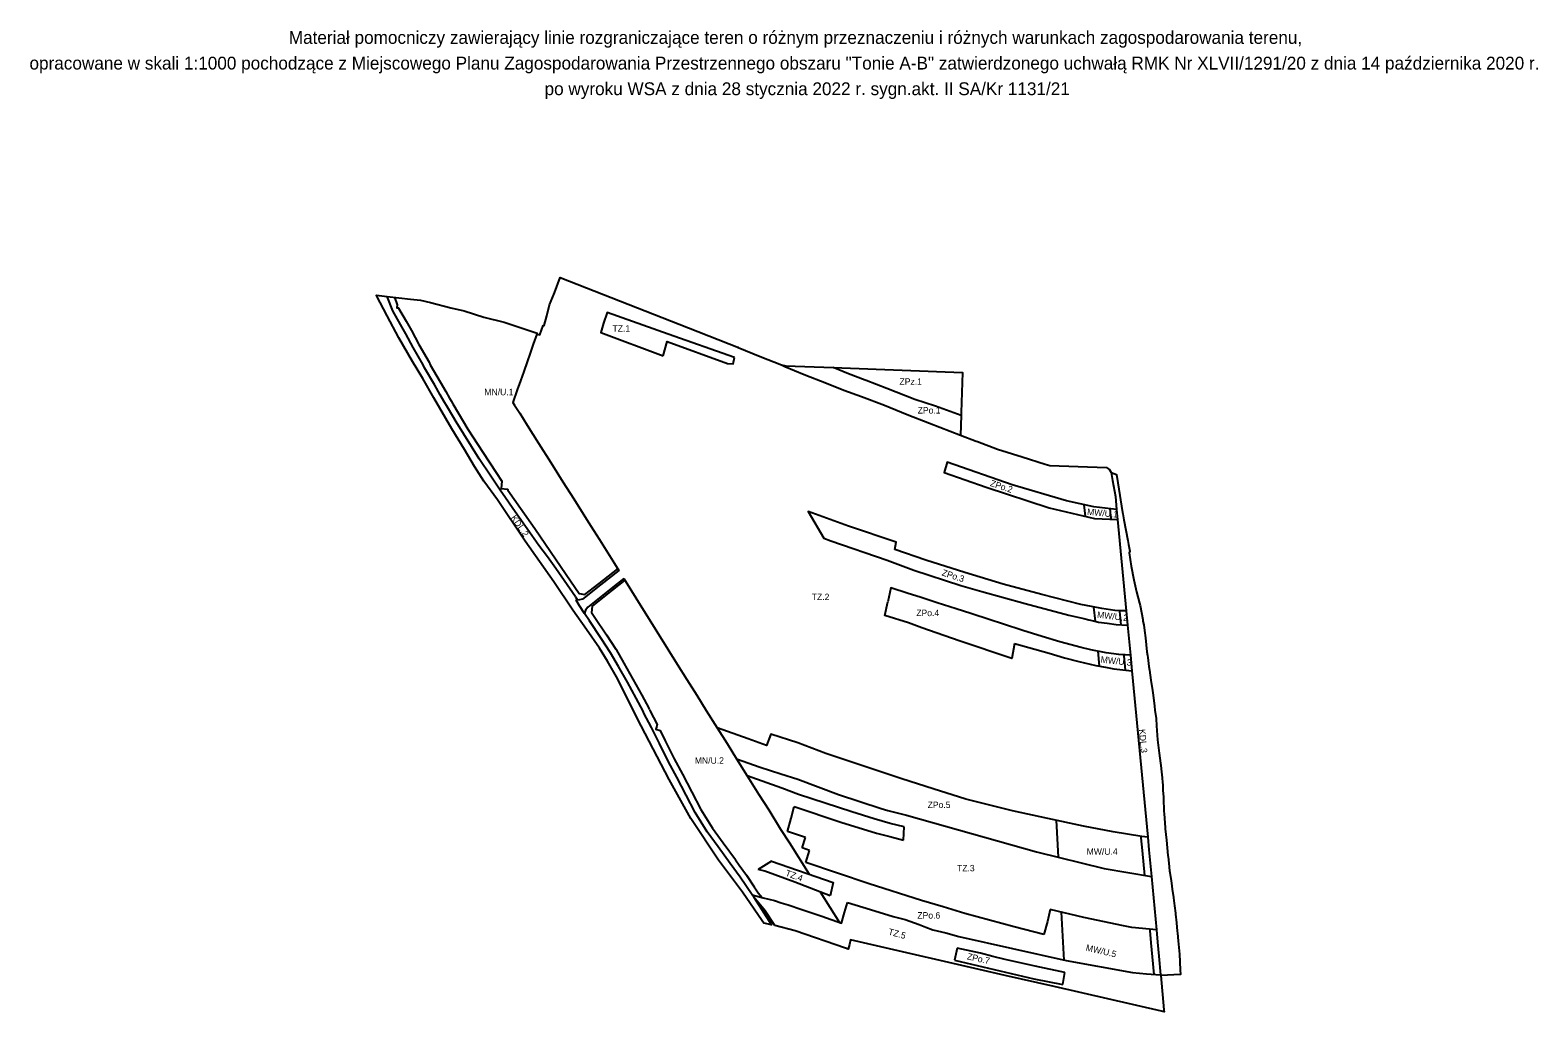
# Model space of a CAD drawing. Extents: x 7421311 to 7422722, y 5551458 to 5553094.
# Drawn here: x 7421311 to 7422722, y 5552175 to 5553094 of the extents above; entities that cross this region are included whole.
import ezdxf

# ---------------------------------------------------------------- set-up
doc = ezdxf.new("R2010")
doc.units = 0
for name, color, linetype in [('info', 7, 'Continuous'), ('linie rozgraniczające', 7, 'Continuous'), ('nieprzekraczalne linie zabudowy', 7, 'Continuous'), ('przeznaczenia terenów', 7, 'Continuous')]:
    doc.layers.add(name, color=color, linetype=linetype)

msp = doc.modelspace()

# ---------------------------------------------------------------- linework, layer by layer
at = {"layer": 'linie rozgraniczające'}
for p, q in [((7421645.3, 5552844.5), (7421645.2, 5552844.5)), ((7421650.5, 5552831), (7421645.3, 5552844.5)), ((7421657.8, 5552818.4), (7421650.5, 5552831)), ((7421662.7, 5552809.7), (7421657.8, 5552818.4)), ((7421669.7, 5552796.7), (7421662.7, 5552809.7)), ((7421679, 5552780.5), (7421669.7, 5552796.7)), ((7421694.9, 5552752.5), (7421689.7, 5552761.5)), ((7421706.6, 5552732.4), (7421701.6, 5552740.9)), ((7421709.7, 5552727.2), (7421706.6, 5552732.4)), ((7421731.4, 5552692.7), (7421709.7, 5552727.2)), ((7421709.7, 5552727.2), (7421709.7, 5552727.2)), ((7421742.2, 5552676.4), (7421731.4, 5552692.7)), ((7421731.4, 5552692.7), (7421731.4, 5552692.7)), ((7422297.1, 5552649.6), (7422298.2, 5552639)), ((7421778.4, 5552624), (7421765, 5552642.9)), ((7422149.2, 5552597.7), (7422120.1, 5552607.9)), ((7422138.1, 5552588.5), (7422182, 5552574)), ((7422185.8, 5552586.3), (7422149.2, 5552597.7)), ((7422182, 5552574), (7422182, 5552574)), ((7422221.5, 5552575.3), (7422185.8, 5552586.3)), ((7422257.9, 5552565.7), (7422221.5, 5552575.3)), ((7421821.4, 5552563.4), (7421823.2, 5552560.3)), ((7421823.2, 5552560.3), (7421823.2, 5552560.3)), ((7422294.3, 5552556.2), (7422257.9, 5552565.7)), ((7422242.3, 5552557.3), (7422283, 5552546.3)), ((7422283, 5552546.3), (7422296.9, 5552543.1)), ((7422304.1, 5552554.3), (7422294.3, 5552556.2)), ((7422326, 5552550.7), (7422313.8, 5552552.4)), ((7422331.4, 5552550.5), (7422326, 5552550.7)), ((7422326, 5552550.7), (7422326, 5552550.7)), ((7422336.7, 5552550.4), (7422331.4, 5552550.5)), ((7421845.4, 5552524.6), (7421834.5, 5552540.9)), ((7422306.2, 5552540.9), (7422310.7, 5552539.9)), ((7422319, 5552538.7), (7422327.2, 5552537.5)), ((7422310.1, 5552512.7), (7422311.5, 5552498.6)), ((7421870, 5552483.5), (7421861.6, 5552498.4)), ((7421878.2, 5552468.6), (7421870, 5552483.5)), ((7421884.9, 5552456.5), (7421878.2, 5552468.6)), ((7422014.5, 5552384.5), (7421982.2, 5552396)), ((7422030, 5552378.5), (7422014.5, 5552384.5)), ((7422080, 5552362.2), (7422030, 5552378.5)), ((7422023.2, 5552356.3), (7422026.1, 5552367.2)), ((7422026.1, 5552367.2), (7422069.8, 5552352.5)), ((7422100.9, 5552355.8), (7422080, 5552362.2)), ((7422019.7, 5552343.9), (7422023.2, 5552356.3)), ((7422069.8, 5552352.5), (7422103, 5552342.4)), ((7422128.2, 5552335.8), (7422128.8, 5552348.1)), ((7422273.4, 5552319.7), (7422271.6, 5552354.4)), ((7422036.6, 5552338.4), (7422019.7, 5552343.9)), ((7422033.6, 5552328.6), (7422036.6, 5552338.4)), ((7422040.3, 5552326.1), (7422033.6, 5552328.6)), ((7422036.8, 5552315), (7422040.3, 5552326.1)), ((7421998.5, 5552306.8), (7421992.2, 5552308.4)), ((7422026.6, 5552296.6), (7421998.5, 5552306.8)), ((7422096.2, 5552295), (7422036.8, 5552315)), ((7422059.8, 5552283.6), (7422026.6, 5552296.6)), ((7422145.1, 5552279.4), (7422096.2, 5552295)), ((7421986.7, 5552284.5), (7421986.7, 5552284.5)), ((7421986.7, 5552284.5), (7421997.1, 5552281.9)), ((7421997.1, 5552281.9), (7422007.6, 5552279.2)), ((7422007.6, 5552279.2), (7422014, 5552277.2)), ((7422014, 5552277.2), (7422020.5, 5552275.1)), ((7422073.1, 5552268.2), (7422075.9, 5552277.4)), ((7422075.9, 5552277.4), (7422097.3, 5552270.9)), ((7422165.5, 5552273.3), (7422145.1, 5552279.4)), ((7422020.5, 5552275.1), (7422033.3, 5552271)), ((7422033.3, 5552271), (7422051.8, 5552264.5)), ((7422097.3, 5552270.9), (7422118.8, 5552264.4)), ((7422265.5, 5552271), (7422262.9, 5552259.6)), ((7422296.9, 5552263.3), (7422265.5, 5552271)), ((7422278.6, 5552223.5), (7422276.2, 5552268.3)), ((7422334.3, 5552255.5), (7422296.9, 5552263.3)), ((7422142.9, 5552256.7), (7422149.3, 5552254.4)), ((7422149.3, 5552254.4), (7422155.8, 5552252)), ((7422155.8, 5552252), (7422167.9, 5552248.9)), ((7422167.9, 5552248.9), (7422180.1, 5552245.7)), ((7422232, 5552254.7), (7422208.9, 5552261)), ((7422259.5, 5552247.5), (7422232, 5552254.7)), ((7422262.9, 5552259.6), (7422259.5, 5552247.5)), ((7422342.1, 5552253.9), (7422334.3, 5552255.5)), ((7422365, 5552251.8), (7422342.1, 5552253.9)), ((7422178.6, 5552234.6), (7422177.2, 5552229)), ((7422200.3, 5552229.9), (7422178.6, 5552234.6)), ((7422180.1, 5552245.7), (7422230.4, 5552234.4)), ((7422259.5, 5552247.5), (7422259.5, 5552247.5)), ((7422177.2, 5552229), (7422175.9, 5552223.5)), ((7422175.9, 5552223.5), (7422213.1, 5552214.8)), ((7422212, 5552227), (7422200.3, 5552229.9)), ((7422213.1, 5552214.8), (7422250.4, 5552206)), ((7422250.4, 5552206), (7422277.3, 5552200.6)), ((7422279.2, 5552211.9), (7422251.5, 5552217.9)), ((7422277.3, 5552200.6), (7422279.2, 5552211.9))]:
    msp.add_line(p, q, dxfattribs=at)
for points in [[(7421988.3, 5552282.4), (7422004.8, 5552256.5), (7421997.8, 5552258.1), (7421996.2, 5552260.4), (7421977.6, 5552287.1), (7421955.1, 5552317.1), (7421929.5, 5552356), (7421909.1, 5552392.4), (7421879.3, 5552449.9), (7421861, 5552486.3), (7421851.4, 5552503.4), (7421843.8, 5552515.5), (7421831.7, 5552533), (7421819.1, 5552551.1), (7421801.3, 5552577.6), (7421774.4, 5552615.6), (7421748.4, 5552654.1), (7421735.8, 5552671.8), (7421727.1, 5552685.5), (7421717.6, 5552701.2), (7421705.9, 5552720.8), (7421689, 5552749.7), (7421678.6, 5552767.7), (7421669.1, 5552783.8), (7421656.2, 5552805.8), (7421645.2, 5552826.4), (7421635.4, 5552845.3), (7421635.3, 5552845.6), (7421645.3, 5552844.5), (7421667, 5552842.1), (7421676.4, 5552841), (7421685.9, 5552838.9), (7421704.7, 5552834), (7421717.2, 5552831), (7421735.7, 5552825.3), (7421754.8, 5552820.5), (7421770.7, 5552815.3), (7421785.5, 5552810.1), (7421785.2, 5552809.4), (7421788, 5552808.5), (7421791.1, 5552817.5), (7421792, 5552817.4), (7421794.6, 5552826.4), (7421797.2, 5552836.6), (7421801.9, 5552847.8), (7421807.1, 5552862.3), (7421927.1, 5552815.3), (7421973.8, 5552796.9), (7421973.7, 5552796.8), (7421994.1, 5552788.5), (7422014.3, 5552780.4), (7422018.2, 5552779.5), (7422062.5, 5552777.9), (7422070.7, 5552777.6), (7422183.5, 5552773.5), (7422182.4, 5552736.1), (7422182.3, 5552733.2), (7422181.7, 5552714.8), (7422196.3, 5552709.2), (7422197.5, 5552708.8), (7422216.4, 5552701.7), (7422239.2, 5552694.6), (7422261, 5552687.5), (7422265.2, 5552686.2), (7422318.4, 5552684.6), (7422320.5, 5552682.9), (7422320.6, 5552682.8), (7422322.7, 5552679.9), (7422327.6, 5552677.8), (7422329, 5552670), (7422333.3, 5552642.3), (7422333.5, 5552641), (7422334.5, 5552635.6), (7422338.1, 5552616.1), (7422338.8, 5552612.3), (7422340, 5552606.1), (7422339.6, 5552604.5), (7422341.3, 5552592), (7422343.8, 5552579.5), (7422346.3, 5552568.1), (7422349.1, 5552557.5), (7422349.7, 5552555.2), (7422352.1, 5552542.2), (7422352.3, 5552540.7), (7422353.2, 5552537.4), (7422353.8, 5552531.8), (7422354.6, 5552525.2), (7422355.3, 5552518.6), (7422356.1, 5552512), (7422356.5, 5552508.6), (7422356.8, 5552506.6), (7422357.8, 5552498.4), (7422358.6, 5552494.8), (7422359.8, 5552485.6), (7422361.3, 5552475.9), (7422362, 5552471.5), (7422363.2, 5552461.3), (7422363.6, 5552457.5), (7422364.8, 5552449.7), (7422365.1, 5552442.6), (7422366.1, 5552429.6), (7422367.5, 5552417.2), (7422369.4, 5552403.1), (7422369.5, 5552402.5), (7422370.3, 5552394.2), (7422370.3, 5552394.2), (7422370.8, 5552389.6), (7422371, 5552387.5), (7422371, 5552385.5), (7422371, 5552385.1), (7422371.1, 5552382.1), (7422371.5, 5552376.4), (7422371.5, 5552375.9), (7422371.6, 5552375.2), (7422372, 5552362.6), (7422372.1, 5552360.7), (7422373, 5552347.3), (7422373, 5552346.4), (7422374.5, 5552335.7), (7422375.6, 5552321.3), (7422375.8, 5552320.1), (7422376.5, 5552314.1), (7422377.2, 5552307.2), (7422377.4, 5552305.5), (7422378.7, 5552297.8), (7422379, 5552295.5), (7422379.8, 5552290), (7422380.9, 5552282.2), (7422380.9, 5552281.9), (7422381.9, 5552274.4), (7422382.8, 5552267.5), (7422382.9, 5552266.5), (7422383.7, 5552258.5), (7422384.4, 5552250.6), (7422384.6, 5552248.7), (7422385.3, 5552241.6), (7422386.4, 5552229), (7422387.2, 5552214.4), (7422387.6, 5552209.9), (7422369, 5552209.1), (7422372, 5552177.1), (7422372.2, 5552175.1), (7422369.8, 5552175.6), (7422269.4, 5552198.7), (7422223.6, 5552209.2), (7422078.7, 5552242.4), (7422077.7, 5552238.2), (7422076.6, 5552233.8), (7422074.2, 5552234.6), (7422026.9, 5552250.9), (7422008, 5552255.8)], [(7421970.1, 5552787.3), (7421908.2, 5552809.2), (7421851.2, 5552829.6), (7421847.7, 5552819.5)], [(7421847.7, 5552819.5), (7421845.2, 5552810.8), (7421903.6, 5552788.9)], [(7421785.2, 5552809.4), (7421781.9, 5552800), (7421779, 5552791.6), (7421776.2, 5552783.5), (7421773, 5552774.3), (7421769.9, 5552765.5), (7421767, 5552757.1), (7421762.9, 5552745.3), (7421764.4, 5552742.9), (7421769.3, 5552735.2), (7421776.2, 5552724.2), (7421786.9, 5552707.2), (7421798.4, 5552689.1), (7421809.7, 5552671.2), (7421819.8, 5552655.1), (7421831.8, 5552636.2), (7421838.4, 5552625.8), (7421843.9, 5552617), (7421858, 5552594.7), (7421862.1, 5552588.2), (7421844.8, 5552574.6), (7421827.9, 5552561.4), (7421825.2, 5552560.5), (7421823.2, 5552560.3)], [(7421903.6, 5552788.9), (7421907.1, 5552802.3), (7421963.7, 5552781.8)], [(7421963.7, 5552781.8), (7421968.9, 5552781.5), (7421970.1, 5552787.3)], [(7421689.7, 5552761.5), (7421680.3, 5552777.8), (7421679, 5552780.5)], [(7422014.3, 5552780.4), (7422017.4, 5552779.1), (7422035.4, 5552771.5), (7422056.2, 5552763.5), (7422072.5, 5552756.9), (7422089.1, 5552750.9), (7422110.6, 5552742.7), (7422131.7, 5552734.1), (7422152.8, 5552726), (7422181.7, 5552714.8)], [(7422182.3, 5552733.2), (7422178.8, 5552734.5), (7422158.2, 5552741.9), (7422138.9, 5552748.2), (7422112.8, 5552758.4), (7422093.4, 5552765.8), (7422092.4, 5552766.2), (7422076.9, 5552772.2), (7422062.5, 5552777.9)], [(7421701.6, 5552740.9), (7421698.4, 5552746.4), (7421694.9, 5552752.5)], [(7422327.7, 5552645.3), (7422306.3, 5552647.6), (7422280.7, 5552653.2), (7422230, 5552668.4), (7422169.2, 5552689.4), (7422166.5, 5552679.7), (7422205.8, 5552666.1), (7422264.7, 5552646.7), (7422307, 5552636.9), (7422328.6, 5552635.9)], [(7421765, 5552642.9), (7421753.3, 5552660), (7421751.7, 5552662.4), (7421742.2, 5552676.4)], [(7422322.7, 5552679.9), (7422323.8, 5552672.2), (7422326.6, 5552657.4), (7422327.7, 5552645.3), (7422328.6, 5552635.9), (7422336.7, 5552550.4), (7422338, 5552536.9), (7422340.6, 5552508.9), (7422342, 5552494.1), (7422356.8, 5552338.5), (7422357.9, 5552326.6), (7422360.2, 5552301.6), (7422365, 5552251.8), (7422366, 5552240.2), (7422367.3, 5552227.1), (7422368.9, 5552209.7), (7422369, 5552209.1)], [(7422076.8, 5552629.6), (7422039.1, 5552643.2), (7422053.7, 5552618.3)], [(7422120.1, 5552607.9), (7422121.5, 5552614.5), (7422076.8, 5552629.6)], [(7421821.4, 5552563.4), (7421802.9, 5552590.1), (7421795.1, 5552600.8), (7421787.2, 5552611.5), (7421778.4, 5552624)], [(7422053.7, 5552618.3), (7422060.2, 5552616), (7422113, 5552597.8), (7422138.1, 5552588.5)], [(7421866.7, 5552580.5), (7421854.7, 5552571.1), (7421832.9, 5552553.9), (7421830.7, 5552551.1), (7421829.8, 5552548)], [(7421866.7, 5552580.5), (7421877.9, 5552562.5), (7421897.4, 5552531.1), (7421907.9, 5552514.4), (7421916.6, 5552500.3), (7421925.7, 5552486), (7421934.9, 5552471.3), (7421943.7, 5552457.2), (7421954.1, 5552440.8), (7421963.3, 5552426.1), (7421972.2, 5552412)], [(7422182, 5552574), (7422201.6, 5552568.3), (7422242.3, 5552557.3)], [(7421834.5, 5552540.9), (7421829.8, 5552548), (7421825.1, 5552555), (7421822.1, 5552560.3), (7421823.2, 5552560.3)], [(7422232.3, 5552519.8), (7422229.7, 5552505.8), (7422180.3, 5552522.4), (7422145.6, 5552534.3), (7422133, 5552539), (7422110.9, 5552545.9), (7422113.8, 5552558.8)], [(7422340.6, 5552508.9), (7422335.6, 5552509.1), (7422329.7, 5552509.6), (7422318, 5552511.2), (7422303.6, 5552514), (7422294.4, 5552516.1), (7422274.5, 5552521.4), (7422258.2, 5552526.4), (7422240, 5552531.9), (7422221, 5552538.2), (7422209.5, 5552541.8), (7422191.4, 5552547.8), (7422177.5, 5552552.3), (7422159.9, 5552557.9), (7422143.8, 5552563), (7422132.7, 5552566.6), (7422116.4, 5552571.9), (7422113.8, 5552558.8)], [(7422313.8, 5552552.4), (7422313.8, 5552552.5), (7422304.1, 5552554.3)], [(7422306.2, 5552553.9), (7422307.5, 5552540.6)], [(7422336.7, 5552550.4), (7422336.7, 5552550.4)], [(7422296.9, 5552543.1), (7422301.7, 5552542), (7422306.2, 5552540.9)], [(7422310.7, 5552539.9), (7422310.8, 5552539.9), (7422319, 5552538.7)], [(7422327.2, 5552537.5), (7422327.3, 5552537.5), (7422332.6, 5552537.2)], [(7422332.6, 5552537.2), (7422337.8, 5552536.9), (7422338, 5552536.9)], [(7421861.6, 5552498.4), (7421854.3, 5552511.2), (7421845.4, 5552524.6)], [(7422232.3, 5552519.8), (7422264.5, 5552510.6), (7422279.1, 5552506.4), (7422292.5, 5552502.9), (7422308.2, 5552499.2), (7422317.4, 5552497.5), (7422325.2, 5552496), (7422342, 5552494.1)], [(7422008, 5552255.8), (7421998.8, 5552269.5), (7421988.3, 5552282.4), (7421986.7, 5552284.5), (7421975.4, 5552301), (7421966.2, 5552314), (7421954.8, 5552329.6), (7421944.6, 5552343.7), (7421933.5, 5552361.5), (7421925.1, 5552377.9), (7421916.4, 5552394.7), (7421908.5, 5552409.1), (7421900, 5552426.1), (7421892.7, 5552441.1), (7421885.5, 5552454.7), (7421884.9, 5552456.5)], [(7422356.8, 5552338.5), (7422351.2, 5552339.2), (7422324.6, 5552343.6), (7422296.6, 5552349), (7422263.5, 5552356.1), (7422230.4, 5552363.2), (7422186.6, 5552374), (7422156, 5552383.7), (7422126.8, 5552393), (7422091.3, 5552404.9), (7422055.7, 5552416.8), (7422029.5, 5552426.8), (7422004.1, 5552435), (7422000.2, 5552424.2), (7421982.9, 5552430.5), (7421954.1, 5552440.8)], [(7421972.2, 5552412), (7421994.1, 5552404.2), (7422013.6, 5552397.8), (7422029.6, 5552392.7), (7422048.6, 5552385.6), (7422067.4, 5552378.6), (7422107.4, 5552365.3), (7422113.7, 5552363.6), (7422131, 5552359), (7422252.8, 5552324.8), (7422316, 5552309.2), (7422360.2, 5552301.6)], [(7421972.2, 5552412), (7421982.2, 5552396), (7421993.1, 5552378.6), (7422002.3, 5552364), (7422013.4, 5552346.2), (7422021.6, 5552333.2), (7422040, 5552304)], [(7422128.8, 5552348.1), (7422122.4, 5552349.7), (7422115.9, 5552351.3), (7422100.9, 5552355.8)], [(7422103, 5552342.4), (7422115.6, 5552339.1), (7422128.2, 5552335.8)], [(7422004.9, 5552316.1), (7421992.2, 5552308.4)], [(7422004.9, 5552316.1), (7422062.5, 5552296.2), (7422059.8, 5552283.6)], [(7422050.5, 5552287.3), (7422068.5, 5552258.7)], [(7422051.8, 5552264.5), (7422070.2, 5552258.1), (7422073.1, 5552268.2)], [(7422118.8, 5552264.4), (7422130, 5552261.4), (7422142.9, 5552256.7)], [(7422208.9, 5552261), (7422185.8, 5552267.2), (7422165.5, 5552273.3)], [(7422230.4, 5552234.4), (7422280.6, 5552223), (7422342.5, 5552212)], [(7422251.5, 5552217.9), (7422223.6, 5552224.1), (7422212, 5552227)], [(7422342.5, 5552212), (7422355.7, 5552210.8), (7422368.9, 5552209.7)]]:
    msp.add_lwpolyline(points, dxfattribs=at)
at = {"layer": 'nieprzekraczalne linie zabudowy'}
for p, q in [((7421859.5, 5552514.2), (7421866.8, 5552501.4)), ((7421866.8, 5552501.4), (7421875.2, 5552486.4))]:
    msp.add_line(p, q, dxfattribs=at)
for points in [[(7421652, 5552843.8), (7421654.7, 5552836.8), (7421654.4, 5552834), (7421655.9, 5552833.8), (7421656, 5552833.6), (7421663, 5552821.4), (7421667.9, 5552812.6), (7421675, 5552799.6), (7421684.4, 5552783.2), (7421685.6, 5552780.5), (7421694.9, 5552764.5), (7421700.1, 5552755.5), (7421703.6, 5552749.4), (7421705, 5552746.8), (7421706.8, 5552743.9), (7421711.8, 5552735.5), (7421720.7, 5552720.4), (7421734.6, 5552698.8), (7421747.2, 5552679.7), (7421752.6, 5552671.7), (7421751.9, 5552664.8), (7421757.7, 5552664.2), (7421758.2, 5552663.4), (7421769.9, 5552646.3), (7421783.3, 5552627.4), (7421812.7, 5552584.2), (7421824.9, 5552566.7), (7421830.3, 5552565.5), (7421843.7, 5552576), (7421861.2, 5552589.6)], [(7422322.6, 5552636.2), (7422321.6, 5552646)], [(7421867.6, 5552579), (7421855.8, 5552569.7), (7421836.9, 5552554.8), (7421836.5, 5552548.7), (7421839.5, 5552544.2), (7421850.3, 5552527.9), (7421859.3, 5552514.5)], [(7422331.9, 5552537.2), (7422330.7, 5552549.8), (7422330.7, 5552550.6)], [(7422335.9, 5552494.8), (7422334.7, 5552508.3), (7422334.6, 5552509.2)], [(7421875.2, 5552486.4), (7421883.4, 5552471.5), (7421890.1, 5552459.4)], [(7421890.6, 5552458.3), (7421891, 5552457), (7421897.9, 5552444), (7421897.1, 5552441.6), (7421897.2, 5552441.6), (7421896.5, 5552439.7), (7421900.7, 5552438.3), (7421905.4, 5552428.7), (7421913.8, 5552411.9), (7421921.7, 5552397.5)], [(7421921.7, 5552397.4), (7421930.4, 5552380.7), (7421938.7, 5552364.5), (7421949.6, 5552347), (7421959.7, 5552333.2), (7421971, 5552317.6)], [(7422354.1, 5552302.6), (7422351.9, 5552326.1), (7422350.8, 5552337.9), (7422350.6, 5552339.3)], [(7421971.1, 5552317.5), (7421974.6, 5552312.5), (7421981.4, 5552302.9), (7421988.7, 5552292.1), (7421992.5, 5552286.5), (7421996, 5552282.2)], [(7422362.9, 5552210.2), (7422361.3, 5552226.5), (7422360.1, 5552239.7), (7422359, 5552251.2), (7422358.9, 5552252.4)]]:
    msp.add_lwpolyline(points, dxfattribs=at)
for centre, start, end in [((7421854.3, 5552511.2), 29.6869, 33.8283), ((7421861.6, 5552498.4), 29.3013, 29.6869), ((7421870, 5552483.5), 28.7503, 29.3013), ((7421884.9, 5552456.5), 17.5713, 29.2358), ((7421916.4, 5552394.7), 27.3126, 28.8352), ((7421966.2, 5552314), 35.404, 36.0317)]:
    msp.add_arc(centre, 6, start, end, dxfattribs=at)

# ---------------------------------------------------------------- texts
at = {"layer": 'info'}
for s, p in [('Materiał pomocniczy zawierający linie rozgraniczające teren o różnym przeznaczeniu i różnych warunkach zagospodarowania terenu, ', (7421553.2, 5553080.9)), ('opracowane w skali 1:1000 pochodzące z Miejscowego Planu Zagospodarowania Przestrzennego obszaru "Tonie A-B" zatwierdzonego uchwałą RMK Nr XLVII/1291/20 z dnia 14 października 2020 r.', (7421310.6, 5553056.9)), ('po wyroku WSA z dnia 28 stycznia 2022 r. sygn.akt. II SA/Kr 1131/21', (7421792.5, 5553032.9))]:
    msp.add_text(s, height=12, dxfattribs=at).set_placement(p)
at = {"layer": 'przeznaczenia terenów'}
for s, p in [('TZ.1', (7421856.1, 5552811.6)), ('MN/U.1', (7421736.2, 5552752.1)), ('ZPz.1', (7422124.6, 5552761.9)), ('ZPo.1', (7422141.6, 5552735)), ('TZ.2', (7422042.5, 5552560.4)), ('ZPo.4', (7422140.3, 5552545.4)), ('MN/U.2', (7421933.1, 5552407.3)), ('ZPo.5', (7422150.9, 5552365.8)), ('MW/U.4', (7422299.7, 5552322.1)), ('TZ.3', (7422178.4, 5552306.6)), ('ZPo.6', (7422141.3, 5552262.4))]:
    msp.add_text(s, height=6, dxfattribs=at).set_placement(p)
for s, rotation, p in [('ZPo.2', 341.7365, (7422208.9, 5552667.3)), ('MW/U.1', 354.6044, (7422299.9, 5552640.2)), ('KDL.2', 305, (7421760.5, 5552637.3)), ('ZPo.3', 342.174, (7422163.7, 5552583.6)), ('MW/U.2', 353.6251, (7422309.2, 5552543.9)), ('MW/U.3', 353.7256, (7422312.6, 5552502)), ('KDL.3', 275, (7422348.6, 5552439.4)), ('TZ.4', 340, (7422017.3, 5552302.6)), ('TZ.5', 345, (7422113.6, 5552247.5)), ('MW/U.5', 346.9395, (7422298.5, 5552232.5)), ('ZPo.7', 347.5833, (7422187.4, 5552224.3))]:
    msp.add_text(s, height=6, rotation=rotation, dxfattribs=at).set_placement(p)

doc.saveas('drawing.dxf')
